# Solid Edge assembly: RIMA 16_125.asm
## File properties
Title: Zylinder
Author: ahadarics
Template: iso metric assembly.asm
Last saved by: ahadarics
Revision: 15
Application: Solid Edge
Username: ahadarics
Dokumentum tartalom típus: 1
Document Number: RIMA 16/125
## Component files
Profilrohr.par
Kolbenstange.par
Kit_1.par
Kit_2.par
Mutter_1.par
Mutter_2.par
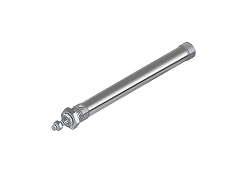
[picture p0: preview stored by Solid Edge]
